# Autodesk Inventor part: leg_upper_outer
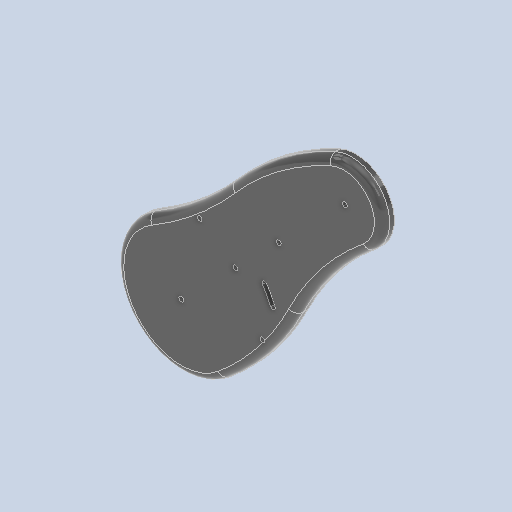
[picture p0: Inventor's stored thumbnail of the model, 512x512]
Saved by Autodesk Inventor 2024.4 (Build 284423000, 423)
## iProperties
Created: 2026-01
Part Number: leg_upper_outer
Material: Generic
Document SubType Name: Modeling
Designer: AdminForWorker
Density: 1 g/cm^3
Appearance: Default
Title: leg_upper_outer
Author: AdminForWorker
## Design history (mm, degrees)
feature "Body1"
body "Solid1"
